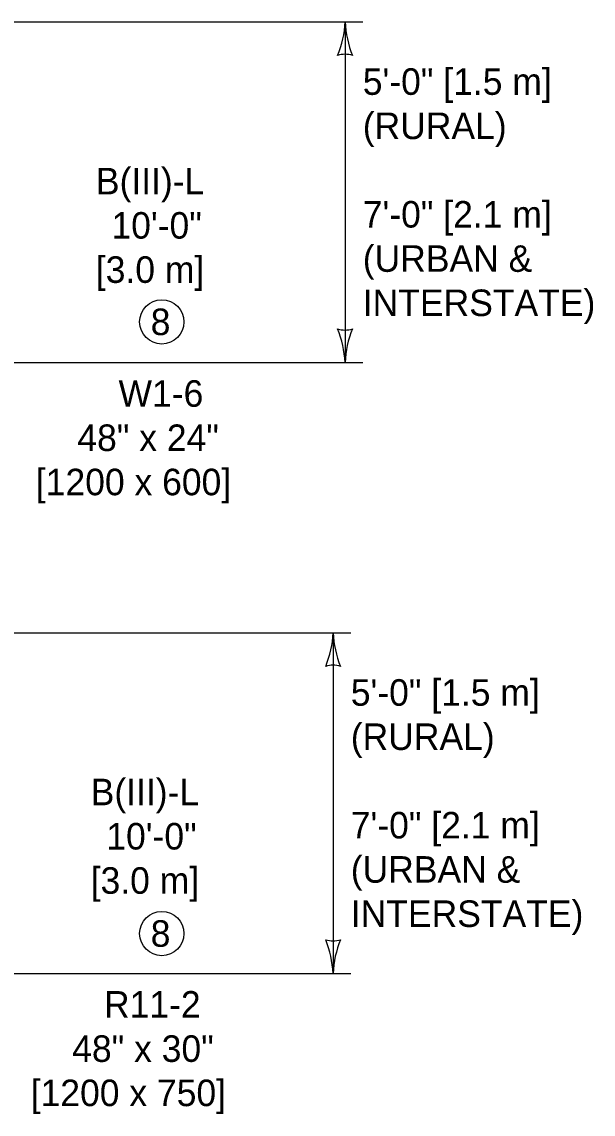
# Model space of a CAD drawing. Extents: x 49991.4 to 50021, y 49987.6 to 50011.4.
# Drawn here: x 50012.933 to 50014.225, y 49990.646 to 49993.114 of the extents above; entities that cross this region are included whole.
import ezdxf

# ---------------------------------------------------------------- set-up
doc = ezdxf.new("R2010")
doc.units = 0
doc.layers.add('Level 2', color=7, linetype='Continuous')
doc.layers.add('Level 3', color=7, linetype='Continuous')

msp = doc.modelspace()

# ---------------------------------------------------------------- linework, layer by layer
at = {"layer": 'Level 2'}
for centre in [(50013.2494, 49992.4361), (50013.2494, 49991.0536)]:
    msp.add_circle(centre, 0.05, dxfattribs=at)
at = {"layer": 'Level 3'}
for p, q in [((50012.5511, 49993.1143), (50013.704, 49993.1143)), ((50013.664, 49993.1143), (50013.664, 49992.3443)), ((50012.5311, 49992.3443), (50013.704, 49992.3443)), ((50012.544, 49991.7336), (50013.6769, 49991.7336)), ((50013.6369, 49991.7336), (50013.6369, 49990.9636)), ((50012.524, 49990.9636), (50013.6769, 49990.9636))]:
    msp.add_line(p, q, dxfattribs=at)
for centre, radius, start, end in [((50013.4419, 49993.1235), 0.2223, 337.456, 357.6395), ((50013.8967, 49993.1258), 0.233, 182.8273, 202.0772), ((50013.664, 49992.9861), 0.0548, 72.1388, 107.8612), ((50013.664, 49992.4725), 0.0548, 252.1388, 287.8612), ((50013.4313, 49992.3328), 0.233, 2.8273, 22.0772), ((50013.8861, 49992.3351), 0.2223, 157.456, 177.6395), ((50013.4148, 49991.7428), 0.2223, 337.456, 357.6395), ((50013.8696, 49991.7451), 0.233, 182.8273, 202.0772), ((50013.6369, 49991.6054), 0.0548, 72.1388, 107.8612), ((50013.6369, 49991.0918), 0.0548, 252.1388, 287.8612), ((50013.4042, 49990.9521), 0.233, 2.8273, 22.0772), ((50013.859, 49990.9544), 0.2223, 157.456, 177.6395)]:
    msp.add_arc(centre, radius, start, end, dxfattribs=at)

# ---------------------------------------------------------------- texts
at = {"layer": 'Level 2'}
for s, p in [('5\'-0" [1.5 m]', (50013.704, 49992.9493)), ('(RURAL)', (50013.704, 49992.8493)), ('B(III)-L', (50013.1005, 49992.7243)), ('7\'-0" [2.1 m]', (50013.704, 49992.6493)), ('10\'-0"', (50013.1357, 49992.6243)), ('(URBAN &', (50013.704, 49992.5493)), ('[3.0 m]', (50013.1004, 49992.5243)), ('INTERSTATE)', (50013.704, 49992.4493)), ('8', (50013.2244, 49992.4063)), ('W1-6', (50013.1517, 49992.2443)), (' 48" x 24"', (50013.0362, 49992.1443)), ('[1200 x 600]', (50012.9648, 49992.0443)), ('5\'-0" [1.5 m]', (50013.6769, 49991.5686)), ('(RURAL)', (50013.6769, 49991.4686)), ('B(III)-L', (50013.0888, 49991.3436)), ('7\'-0" [2.1 m]', (50013.6769, 49991.2686)), ('10\'-0"', (50013.124, 49991.2436)), ('(URBAN &', (50013.6769, 49991.1686)), ('[3.0 m]', (50013.0887, 49991.1436)), ('INTERSTATE)', (50013.6769, 49991.0686)), ('8', (50013.2244, 49991.0238)), ('R11-2', (50013.1188, 49990.8636)), (' 48" x 30"', (50013.0246, 49990.7636)), ('[1200 x 750]', (50012.9531, 49990.6636))]:
    msp.add_text(s, height=0.06, dxfattribs=at).set_placement(p)

doc.saveas('drawing.dxf')
